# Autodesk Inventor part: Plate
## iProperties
Shininess: 20.0
Length Units: 11269
Angle Units: 11279
Time Units: 11290
Mass Units: 11283
Length Display Precision: 3
Angle Display Precision: 2
Created: 2002-08
Part Number: Plate
Material: ABS Plastic
Document SubType Name: Modellieren
Designer: MP
Description: Plate 2x4 (3020) white
Catalog Web Link: www.iBricks.de
Vendor: The LEGO Group
Density: 0.0
Volumn: 0.0
Area: 0.0
PropertySet Name: Model Information
Control State: 0
Master: False
Checked Out: False
Author: Michael Puschner
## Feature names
1. Body [Extrusion]
2. Shell
3. Stud [Extrusion]
4. StudFillet [Fillet]
5. Studs [Rectangular Pattern]
6. InnerStud [Extrusion]
7. InnerStuds [Rectangular Pattern]
8. SmallStud [Extrusion]
9. SmallStuds [Rectangular Pattern]
10. BodyFillet [Fillet]
